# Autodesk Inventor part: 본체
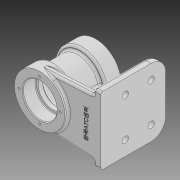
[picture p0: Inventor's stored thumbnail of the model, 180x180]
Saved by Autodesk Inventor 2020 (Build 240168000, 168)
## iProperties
Created: 2024-02
Part Number: 본체
Material: 일반
Document SubType Name: Modeling
Designer: oem
Density: 1 g/cm^3
Appearance: 기본값
Mass: 266.574 g
Surface Area: 647.21 cm^2
Volume: 266.574 cm^3
Author: oem
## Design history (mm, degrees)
sketch "스케치1"
  geometry: C1 r 35 at (0, 0); C2 r 28.5 at (0, 0); 1 further point
  constraints: 2 centre point, 2 coincident
  dimensions: "d0" = 70 diameter of C1; "d1" = 57 diameter of C2
extrude "돌출1" new body sketch "스케치1" stored distance "d2" = 34; taper "d3" = 0 deg
sketch "스케치2"
  geometry: C1 r 28.5 at (0, 0) reference; C2 r 35 at (0, 0)
  constraints: 1 centre point, 1 coincident
  dimensions: "d4" = 70 diameter of C2
extrude "돌출2" join sketch "스케치2" distance "d5" = 22; taper "d6" = 0 deg
sketch "스케치3"
  geometry: C1 r 28.5 at (0, 0) reference; C2 r 35 at (0, 0)
  constraints: 1 centre point, 1 coincident
extrude "돌출3" join sketch "스케치3" distance "d7" = 22; taper "d8" = 0 deg
node "작업 평면1"
sketch "스케치4"
  geometry: L1 (70, -47)-(80, -47); L2 (80, -47)-(80, 47); L3 (80, 47)-(70, 47); L4 (70, 47)-(70, -47); L5 (70, -47)-(80, 47); L6 (80, -47)-(70, 47); 2 further points
  constraints: 12 end point, 2 midpoint, 2 parallel, 1 horizontal, 1 perpendicular
  dimensions: "d10" = 10 distance of L3.end L2.end; "d11" = 94 distance of L2.end L1.end; "d12" = 80 distance from line of point (0, 0) L2
extrude "돌출4" join sketch "스케치4" distance "d13" = 90; taper "d14" = 0 deg
sketch "스케치5"
  geometry: L1 (0, 94)-(0, 0) reference; L2 (0, 94)-(-90, 94) reference; L3 (-90, 0)-(-90, 94) reference; L4 (0, 0)-(-90, 0) reference; L5 (0, 0)-(0, 94) reference; L6 (0, 42)-(-78, 42); L7 (-78, 42)-(-78, 52); L8 (-78, 52)-(0, 52); L9 (0, 52)-(0, 42); 1 further point
  constraints: 8 end point, 2 parallel, 1 horizontal, 1 perpendicular, 1 point on line
  dimensions: "d15" = 78 distance of L7.end L8.end; "d16" = 10 distance of L6.end L7.end; "d17" = 5 distance from line of point (-34, 47) L8
sketch "스케치6"
  geometry: L1 (-28.5, 17)-(-35, 17) reference; L2 (-35, 17)-(-35, 39) reference; L3 (-35, 39)-(35, 39) reference; L4 (35, 39)-(35, 17) reference; L5 (35, 17)-(28.5, 17) reference; L6 (28.5, 17)-(28.5, -17) reference; L7 (28.5, -17)-(35, -17) reference; L8 (35, -17)-(35, -39) reference; L9 (35, -39)-(-35, -39) reference; L10 (-35, -39)-(-35, -17) reference; L11 (-35, -17)-(-28.5, -17) reference; L12 (-28.5, -17)-(-28.5, 17) reference; L13 (-70, 34)-(-70, -56) reference; L14 (-70, -56)-(-80, -56) reference; L15 (-80, -56)-(-80, 34) reference; L16 (-80, 34)-(-70, 34) reference; L17 (-70, 34)-(-80, 34) reference; L18 (-70, 34)-(-28.5, 34); L19 (-70, 34)-(-70, -56) reference; L20 (-70, -44)-(-28.5, -28.895); L21 (-70, -44)-(-21.567, -44); L22 (-28.5, -28.895)-(-28.5, 34); L23 (-70, 34)-(-70, -44); 4 further points
  constraints: 10 end point, 2 horizontal, 2 point on line, 1 collinear
  dimensions: "d18" = 20 deg angle of L21 L20; "d19" = 12 distance of L13.end L20.start
extrude "돌출5" join sketch "스케치6" stored distance "d20" = 10; taper "d21" = 0 deg
sketch "스케치7"
  geometry: L1 (70, 47)-(70, 5) reference; L2 (70, 39)-(-1.969, 34.945); 2 further points
  constraints: 2 end point, 1 point on line, 5 other
  dimensions: "d22" = 8 distance of L1.start L2.start
feature "리브1" sketch "스케치7" dims "d24" = 1, "d25" = 10, "d26" = 0, "d27" = 0, "d28" = 1, "d29" = 1
sketch "스케치8"
  geometry: L1 (90, 94)-(0, 94) reference; L2 (90, 8)-(90, 0) reference; L3 (90, 94)-(90, 86) reference; L4 (0, 94)-(0, 0) reference; L5 (0, 47)-(90, 47); L6 (90, 0)-(90, 94) reference; L7 (90, 0)-(0, 0) reference; C1 r 10 at (20, 74); C2 r 4.5 at (20, 74); C3 r 4.5 at (20, 20); C4 r 10 at (20, 20); C5 r 4.5 at (56, 74); C6 r 10 at (56, 74); C7 r 4.5 at (56, 20); C8 r 10 at (56, 20); 1 further point
  constraints: 8 centre point, 4 coincident, 2 end point, 2 midpoint, 2 symmetric about line, 2 other
  dimensions: "d30" = 20 diameter of C1; "d31" = 9 diameter of C2; "d32" = 20 distance from line of L1 C1.centre; "d34" = 70 distance from line of L3 C1.centre; "d35" = 70 distance from line of L6 C3.centre (derived); "d36" = 20 diameter of C6; "d37" = 9 diameter of C5; "d38" = 34 distance from line of L6 C6.centre; "d39" = 34 distance from line of L2 C7.centre; "d40" = 36 distance of C5.centre C1.centre; "d41" = 36 distance of C3.centre C8.centre
extrude "돌출6" cut sketch "스케치8" extent not by distance; stored distance "d42" = 92.271; taper "d43" = 0 deg
extrude "돌출7" join sketch "스케치8" distance "d44" = 3; taper "d45" = 0 deg
fillet "모깎기1" dims "d46" = 20
node "작업 평면2"
sketch "스케치9"
  geometry: C1 r 6 at (0, 0); 1 further point
  constraints: 1 centre point, 1 coincident
  dimensions: "d48" = 12 diameter of C1
extrude "돌출8" join sketch "스케치9" distance "d49" = 6; taper "d50" = 0 deg
sketch "스케치10"
  geometry: L1 (-28.5, 17)-(-28.5, -17) reference; L2 (35, -17)-(35, -39) reference; L3 (35, -39)-(-35, -39) reference; L4 (-35, -39)-(-35, -31.261) reference; L5 (-35, -31.261)-(-70, -44) reference; L6 (-70, -44)-(-70, -56) reference; L7 (-70, -56)-(-80, -56) reference; L8 (-80, -56)-(-80, 34) reference; L9 (-80, 34)-(-35, 34) reference; L10 (-35, 34)-(-35, 39) reference; L11 (-35, 39)-(35, 39) reference; L12 (35, 39)-(35, 17) reference; L13 (35, 17)-(28.5, 17) reference; L14 (28.5, 17)-(28.5, 6) reference; L15 (28.5, 6)-(31.5, 6) reference; L16 (31.5, 6)-(31.5, -6) reference; L17 (31.5, -6)-(28.5, -6) reference; L18 (28.5, -6)-(28.5, -17) reference; L19 (28.5, -17)-(35, -17) reference; L20 (35, 39)-(-35, 39) reference; L21 (0, 39)-(0, -39); L22 (23.5, 15)-(0, 15); L23 (0, -15)-(23.5, -15); L24 (23.5, -15)-(23.5, 15); L25 (23.5, 39)-(23.5, 21); L26 (23.5, 21)-(0, 21); L27 (23.5, 39)-(0, 39); L28 (20, 21)-(20, 15); L29 (31.5, 0)-(0, 0); L30 (23.5, -39)-(23.5, -21); L31 (23.5, -21)-(0, -21); L32 (23.5, -39)-(0, -39); L33 (20, -15)-(20, -21); 3 further points
  constraints: 26 end point, 8 point on line, 4 perpendicular, 3 midpoint, 3 symmetric about line, 2 horizontal, 1 collinear, 1 parallel
  dimensions: "d53" = 23.5 distance of L22.end L22.start; "d54" = 18 distance of L25.start L25.end; "d55" = 40 diameter of L28 L21; "d56" = 47 diameter of L30.start L21; "d57" = 40 diameter of L33 L21
revolve "회전1" sketch "스케치10" stored, may be unused: angle "d58" = 90 deg
fillet "모깎기2" dims "d59" = 3
fillet "모깎기3" dims "d60" = 1
chamfer "모따기1" distance "d61" = 1; stored, may be unused: second distance "d62" = 2, angle "d63" = 45 deg
sketch "스케치11"
  geometry: C1 r 24.5 at (0, 0) reference; A1 r 28.5 centre (0, 0) between (-28.5, 0) and (28.5, 0); A2 r 28.5 centre (0, 0) between (-28.5, 0) and (0, 28.5) reference; 2 further points
  constraints: 4 point on circle, 1 centre point, 1 coincident
  dimensions: "d64" = 57 diameter of A1
hole "구멍1" sketch "스케치11" at (-28.5, 0), (0, 28.5), (0, -28.5), (28.5, 0) diameter "d65" = 3.242; stored, may be unused: countersink angle "d69" = 90 deg, drill point angle "d71" = 118 deg; dims "d66" = 8, "d67" = 10, "d68" = 3, "d70" = 10
sketch "스케치12"
  geometry: C1 r 6 at (0, 0) reference; 1 further point
  constraints: 1 coincident
hole "구멍2" sketch "스케치12" at (0, 0) diameter "d72" = 5.1881; stored, may be unused: countersink angle "d76" = 90 deg, drill point angle "d78" = 0 deg; dims "d73" = 16, "d74" = 7, "d75" = 2, "d77" = 16
sketch "스케치13"
  geometry: L1 (-25.685, 24.121)-(-32.628, 24.121); L2 (-32.628, 24.121)-(-32.628, -24.121); L3 (-32.628, -24.121)-(-25.685, -24.121); L4 (-25.685, -24.121)-(-25.685, 24.121); L5 (-25.685, 24.121)-(-32.628, -24.121); L6 (-32.628, 24.121)-(-25.685, -24.121); 2 further points
  constraints: 12 end point, 2 midpoint, 2 parallel, 1 horizontal, 1 perpendicular
extrude "돌출9" join sketch "스케치13" stored distance "d83" = 10; taper "d84" = 0 deg
fillet "모깎기12" dims "d89" = 3
fillet "모깎기13" dims "d90" = 3
fillet "모깎기14" dims "d91" = 3
fillet "모깎기15" dims "d92" = 3
fillet "모깎기16" dims "d93" = 3
fillet "모깎기17" dims "d94" = 3
fillet "모깎기18" dims "d95" = 3
fillet "모깎기19" dims "d96" = 3
fillet "모깎기20" dims "d97" = 3
fillet "모깎기21" dims "d98" = 3
fillet "모깎기22" dims "d99" = 3
fillet "모깎기23" dims "d100" = 3
sketch "스케치14"
  geometry: L1 (80, -44)-(80, 44) reference; L2 (18.661, 33.102)-(67.338, 35.845) reference; L3 (18.661, -33.102)-(67, -35.826) reference; L4 (60, -35.432)-(60, 35.432); L5 (80, 27)-(80, -27) reference; L6 (80, 0)-(39.026, 0); L7 (56.737, -21.086)-(56.737, 20.393); L8 (56.737, 20.393)-(62.741, 20.393); L9 (62.741, 20.393)-(62.741, -21.086); L10 (62.741, -21.086)-(56.737, -21.086); A1 r 38 centre (1.026, 0) between (38.973, -2) and (38.973, 2) reference
  constraints: 4 end point, 2 point on line, 1 horizontal, 1 midpoint, 1 point on circle, 1 vertical, 2 other
  dimensions: "d101" = 20 distance between parallel lines of L1 L4
feature "엠보싱1" sketch "스케치14" dims "d102" = 0.5, "d103" = 0
node "솔리드1"
mirror "미러1"
mirror "미러2"
node "절단 모서리 투영1"
node "절단 모서리 투영2"
feature "A9D066F2-1C7D-4E18-AEED-F7BC21143FA4" dims "d65" = 3.242, "d66" = 8, "d67" = 10, "d68" = 3, "d69" = 90 deg, "d70" = 10, "d71" = 118 deg
other parameters: "d9" = -5, "d47" = -31.5
